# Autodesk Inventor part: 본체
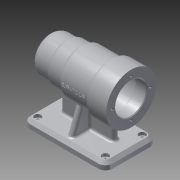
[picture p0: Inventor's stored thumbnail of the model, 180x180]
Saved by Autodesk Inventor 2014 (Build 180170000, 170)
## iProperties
Created: 2016-06
Part Number: 본체
Material: 알루미늄 6061
Document SubType Name: Modeling
Designer: L6
Density: 2.71 g/cm^3
Appearance: 알루미늄 - 평지
Mass: 670.338 g
Surface Area: 648.189 cm^2
Volume: 247.357 cm^3
Author: L6
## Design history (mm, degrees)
sketch "스케치1"
  geometry: L1 (-56, -35)-(56, -35); L2 (56, -35)-(56, 35); L3 (56, 35)-(-56, 35); L4 (-56, 35)-(-56, -35); L5 (-56, -35)-(56, 35); L6 (56, -35)-(-56, 35); 1 further point
  constraints: 12 end point, 2 midpoint, 2 parallel, 1 horizontal, 1 perpendicular
  dimensions: "d0" = 112 distance of L2.end L3.end; "d1" = 70 distance of L1.end L2.end
extrude "돌출1" new body sketch "스케치1" distance "d2" = 10; taper "d3" = 0 deg
sketch "스케치2"
  geometry: L1 (-36, 4)-(36, 4); L2 (36, 4)-(36, -4); L3 (36, -4)-(-36, -4); L4 (-36, -4)-(-36, 4); L5 (-36, 4)-(36, -4); L6 (36, 4)-(-36, -4); 1 further point
  constraints: 12 end point, 2 midpoint, 2 parallel, 1 horizontal, 1 perpendicular
  dimensions: "d4" = 72 distance of L1.start L1.end; "d5" = 8 distance of L1.end L2.end
extrude "돌출2" join sketch "스케치2" distance "d6" = 60; taper "d7" = 0 deg
sketch "스케치3"
  geometry: L1 (-35, 0)-(-35, 10) reference; L2 (35, 0)-(35, 10) reference; L3 (-28, 10)-(28, 10); L4 (28, 10)-(6.162, 70); L5 (6.162, 70)-(-6.162, 70); L6 (-6.162, 70)-(-28, 10); L7 (35, 0)-(-35, 0) reference; L8 (35, 10)-(-35, 10) reference; 1 further point
  constraints: 8 end point, 1 parallel, 1 perpendicular
  dimensions: "d8" = 7 distance from line of L1 L3.start; "d9" = 7 distance from line of L3.end L2; "d10" = 10 distance between parallel lines of L7 L3; "d11" = 110 deg angle of L8 L6; "d12" = 110 deg angle of L8 L4; "d13" = 60 distance between parallel lines of L3 L5
extrude "돌출3" join sketch "스케치3" stored distance "d14" = 8; taper "d15" = 0 deg
sketch "스케치4"
  geometry: L1 (0, 0)-(-10, 0) reference; L2 (0, 35)-(-70, 35); C1 r 34 at (-70, 35)
  constraints: 2 end point, 1 centre point, 1 coincident, 1 parallel
  dimensions: "d16" = 70 distance of L2.start L2.end; "d17" = 68 diameter of C1
extrude "돌출4" join sketch "스케치4" distance "d18" = 28; taper "d19" = 0 deg
sketch "스케치5"
  geometry: C1 r 30 at (70, 35); A1 r 34 centre (70, 35) between (36.236, 31) and (36.236, 39) reference; 1 further point
  constraints: 1 centre point, 1 coincident
  dimensions: "d20" = 60 diameter of C1
extrude "돌출5" join sketch "스케치5" distance "d21" = 39; taper "d22" = 0 deg
sketch "스케치6"
  geometry: C1 r 27 at (70, 35); A1 r 30 centre (70, 35) between (40.268, 31) and (40.268, 39) reference; 1 further point
  constraints: 1 centre point, 1 coincident
  dimensions: "d23" = 54 diameter of C1
extrude "돌출6" join sketch "스케치6" distance "d24" = 20; taper "d25" = 0 deg
sketch "스케치7"
  geometry: C1 r 25 at (70, 35); A1 r 27 centre (70, 35) between (43.298, 31) and (43.298, 39) reference; 1 further point
  constraints: 1 centre point, 1 coincident
  dimensions: "d26" = 50 diameter of C1
extrude "돌출7" join sketch "스케치7" distance "d27" = 25; taper "d28" = 0 deg
fillet "모깎기1" dims "d29" = 10
sketch "스케치8"
  geometry: C1 r 34 at (0, 0) reference; C2 r 21 at (0, 0); 1 further point
  constraints: 1 centre point, 1 coincident
  dimensions: "d30" = 42 diameter of C2
extrude "돌출8" cut sketch "스케치8" distance "d31" = 15; taper "d32" = 0 deg
sketch "스케치9"
  geometry: C1 r 21 at (0, 0) reference; C2 r 24 at (0, 0); 1 further point
  constraints: 1 centre point, 1 coincident
  dimensions: "d33" = 48 diameter of C2
extrude "돌출9" cut sketch "스케치9" distance "d34" = 54; taper "d35" = 0 deg
sketch "스케치10"
  geometry: C1 r 24 at (0, 0) reference; C2 r 21 at (0, 0); 1 further point
  constraints: 1 centre point, 1 coincident
  dimensions: "d36" = 42 diameter of C2
extrude "돌출10" cut sketch "스케치10" distance "d37" = 12; taper "d38" = 0 deg
sketch "스케치11"
  geometry: C1 r 21 at (0, 0) reference; C2 r 17.5 at (0, 0); 1 further point
  constraints: 1 centre point, 1 coincident
  dimensions: "d39" = 35 diameter of C2
extrude "돌출11" cut sketch "스케치11" distance "d40" = 18; taper "d41" = 0 deg
sketch "스케치12"
  geometry: C1 r 17.5 at (0, 0) reference; C2 r 16 at (0, 0); 1 further point
  constraints: 1 centre point, 1 coincident
  dimensions: "d42" = 32 diameter of C2
extrude "돌출12" cut sketch "스케치12" distance "d43" = 4; taper "d44" = 0 deg
sketch "스케치13"
  geometry: C1 r 16 at (0, 0) reference; C2 r 10.5 at (0, 0); 1 further point
  constraints: 1 centre point, 1 coincident
  dimensions: "d45" = 21 diameter of C2
extrude "돌출13" cut sketch "스케치13" distance "d46" = 3; taper "d47" = 0 deg
fillet "모깎기2" dims "d48" = 10
sketch "스케치15"
  geometry: A1 r 10 centre (-46, 25) between (-46, 35) and (-56, 25) reference; A2 r 10 centre (-46, -25) between (-56, -25) and (-46, -35) reference; A3 r 10 centre (46, -25) between (46, -35) and (56, -25) reference; A4 r 10 centre (46, 25) between (56, 25) and (46, 35) reference; 1 further point
hole "구멍1" sketch "스케치15" at (-46, -25), (46, -25), (46, 25), (-46, 25) diameter "d49" = 5; stored, may be unused: countersink angle "d53" = 90 deg, drill point angle "d55" = 118 deg; dims "d50" = 6, "d51" = 9, "d52" = 4, "d54" = 8
chamfer "모따기1" distance "d56" = 1; stored, may be unused: second distance "d57" = 2, angle "d58" = 45 deg
fillet "모깎기3" dims "d59" = 3
fillet "모깎기4" dims "d60" = 0.3
fillet "모깎기5" dims "d61" = 3
sketch "스케치16"
  geometry: L1 (0, 0)-(0, 26); C1 r 22 at (0, 0) reference; 2 further points
  constraints: 2 end point, 1 coincident, 1 vertical
  dimensions: "d62" = 26 distance of L1.start L1.end
hole "구멍2" sketch "스케치16" at (0, 26) diameter "d63" = 3.242; stored, may be unused: countersink angle "d67" = 90 deg, drill point angle "d69" = 118 deg; dims "d64" = 8, "d65" = 9, "d66" = 4, "d68" = 11
chamfer "모따기2" distance "d73" = 4; stored, may be unused: second distance "d74" = 2, angle "d75" = 45 deg
fillet "모깎기6" dims "d76" = 3
fillet "모깎기7" dims "d77" = 3
fillet "모깎기8" dims "d78" = 3
fillet "모깎기9" dims "d79" = 4
fillet "모깎기10" dims "d80" = 3
fillet "모깎기11" dims "d81" = 3
fillet "모깎기12" dims "d82" = 3
node "작업 평면1"
sketch "스케치17"
  geometry: L1 (56, 104)-(56, 36) reference; 2 further points
  constraints: 1 other
  dimensions: "d84" = 48 distance from line of L1 point (8, 70); "d85" = 70 vertical distance of point (0, 0) point (8, 70)
feature "엠보싱1" sketch "스케치17" dims "d86" = 0.5, "d87" = 0
fillet "모깎기13" dims "d90" = 3
node "솔리드1"
pattern_circular "원형 패턴1" dims angle "d71" = 360 deg
other parameters: "d83" = -42.5
